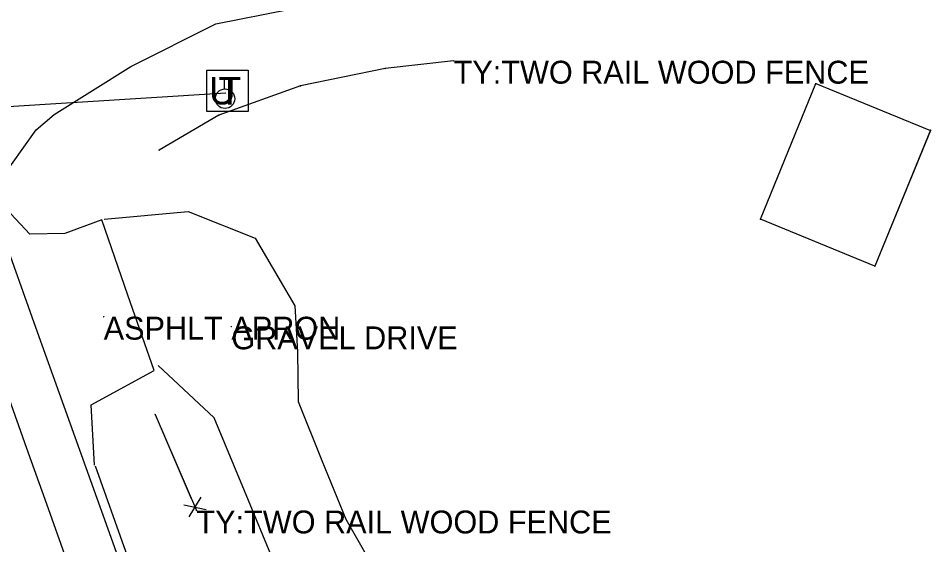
# Model space of a CAD drawing. Extents: x 1050807 to 1053552, y 395828 to 398415.
# Drawn here: x 1052115 to 1052314.1, y 397684.6 to 397799.4 of the extents above; entities that cross this region are included whole.
import ezdxf

# ---------------------------------------------------------------- set-up
doc = ezdxf.new("R2010")
doc.units = 0
for name, color, linetype in [('Default', 7, 'Continuous'), ('S_BUILDING', 7, 'Continuous'), ('S_DRIVEWAY', 7, 'Continuous'), ('S_EDGE_PAVEMENT', 7, 'Continuous'), ('S_FENCE', 7, 'Continuous'), ('S_FENCE_ANNOT', 7, 'Continuous'), ('S_MSC_PT_SYM', 7, 'Continuous'), ('S_PAVEMENT_CROWN', 7, 'Continuous'), ('S_SHOULDER', 7, 'Continuous'), ('S_STR_PT_SYM', 7, 'Continuous'), ('S_SURVEY_TEXT_ANNOT', 7, 'Continuous'), ('S_TELEPHONE_UTILITIES', 7, 'Continuous'), ('S_UNDERGROUND_CABLE', 7, 'Continuous'), ('S_UTILITY_POLE', 7, 'Continuous')]:
    doc.layers.add(name, color=color, linetype=linetype)

msp = doc.modelspace()

# ---------------------------------------------------------------- linework, layer by layer
at = {"layer": 'S_BUILDING'}
for p, q in [((1052276.93, 397755.59), (1052289.06, 397785.2)), ((1052289.06, 397785.2), (1052314.05, 397774.96)), ((1052314.07, 397775.01), (1052301.91, 397745.35)), ((1052314.05, 397774.96), (1052301.91, 397745.35)), ((1052301.91, 397745.35), (1052276.93, 397755.59))]:
    msp.add_line(p, q, dxfattribs=at)
at = {"layer": 'S_DRIVEWAY'}
for points in [[(1052133.67, 397755.55), (1052152.05, 397757.22), (1052166.68, 397751.47), (1052175.35, 397736.7), (1052175.93, 397726.65), (1052176.02, 397715.78), (1052181.24, 397702.97), (1052186.46, 397690.16), (1052194.09, 397676.73), (1052201.72, 397663.29), (1052214.22, 397644.23), (1052221.51, 397635.12)], [(1052214.75, 397627.33), (1052200.49, 397644.3), (1052189.4, 397657.53), (1052178.32, 397670.77), (1052170.98, 397680.3), (1052164.34, 397696.29), (1052157.7, 397712.28), (1052145.51, 397723.65)]]:
    msp.add_lwpolyline(points, dxfattribs=at)
at = {"layer": 'S_EDGE_PAVEMENT'}
for points in [[(1052214.47, 397461.1), (1052206.55, 397483.78), (1052198.62, 397506.45), (1052191.75, 397526.31), (1052184.88, 397546.16), (1052177.39, 397567.38), (1052169.89, 397588.61), (1052165.61, 397600.65), (1052161.33, 397612.68), (1052157.05, 397624.72), (1052152.78, 397636.76), (1052148.47, 397648.84), (1052144.17, 397660.93), (1052139.87, 397673.02), (1052135.57, 397685.11), (1052127.35, 397708.02), (1052119.13, 397730.93), (1052110.86, 397754.03), (1052102.59, 397777.13), (1052095.71, 397795.99), (1052088.82, 397814.85)], [(1052131.61, 397701.92), (1052130.86, 397715.11), (1052144.6, 397722.59), (1052138.9, 397739), (1052133.2, 397755.41), (1052125.14, 397752.48), (1052117.48, 397752.33), (1052113.34, 397756.77), (1052110.71, 397763.72), (1052118.88, 397775.06), (1052122.78, 397778.38), (1052139.51, 397788.91), (1052158.09, 397798.17), (1052174.27, 397801.39)]]:
    msp.add_lwpolyline(points, dxfattribs=at)
at = {"layer": 'S_FENCE'}
for p, q in [((1052195.02, 397788.44), (1052176.57, 397784.66)), ((1052209.98, 397790.14), (1052195.02, 397788.44)), ((1052176.57, 397784.66), (1052158.73, 397778.28)), ((1052158.73, 397778.28), (1052145.72, 397770.67)), ((1052144.85, 397712.99), (1052153.84, 397692.03)), ((1052154.84, 397694.91), (1052152.2, 397690.66)), ((1052154.84, 397694.91), (1052152.2, 397690.66)), ((1052151.07, 397693.29), (1052155.97, 397692.27)), ((1052151.07, 397693.29), (1052155.97, 397692.27))]:
    msp.add_line(p, q, dxfattribs=at)
for points in [[(1052195.02, 397788.44), (1052176.57, 397784.66)], [(1052195.02, 397788.44), (1052176.57, 397784.66)], [(1052209.98, 397790.14), (1052195.02, 397788.44)], [(1052209.98, 397790.14), (1052195.02, 397788.44)], [(1052176.57, 397784.66), (1052158.73, 397778.28)], [(1052176.57, 397784.66), (1052158.73, 397778.28)], [(1052158.73, 397778.28), (1052145.72, 397770.67)], [(1052158.73, 397778.28), (1052145.72, 397770.67)], [(1052144.85, 397712.99), (1052152.73, 397694.62)], [(1052144.85, 397712.99), (1052152.73, 397694.62)]]:
    msp.add_lwpolyline(points, dxfattribs=at)
at = {"layer": 'S_MSC_PT_SYM'}
for points in [[(1052195.02, 397788.44), (1052195.02, 397788.49), (1052195.02, 397788.44), (1052194.97, 397788.44), (1052195.02, 397788.44), (1052195.02, 397788.39), (1052195.02, 397788.44), (1052195.07, 397788.44)], [(1052209.98, 397790.14), (1052209.98, 397790.19), (1052209.98, 397790.14), (1052209.93, 397790.14), (1052209.98, 397790.14), (1052209.98, 397790.09), (1052209.98, 397790.14), (1052210.03, 397790.14)], [(1052176.57, 397784.66), (1052176.57, 397784.71), (1052176.57, 397784.66), (1052176.52, 397784.66), (1052176.57, 397784.66), (1052176.57, 397784.61), (1052176.57, 397784.66), (1052176.62, 397784.66)], [(1052158.73, 397778.28), (1052158.73, 397778.33), (1052158.73, 397778.28), (1052158.68, 397778.28), (1052158.73, 397778.28), (1052158.73, 397778.23), (1052158.73, 397778.28), (1052158.78, 397778.28)], [(1052145.72, 397770.67), (1052145.72, 397770.72), (1052145.72, 397770.67), (1052145.67, 397770.67), (1052145.72, 397770.67), (1052145.72, 397770.62), (1052145.72, 397770.67), (1052145.77, 397770.67)], [(1052133.6, 397734.3), (1052133.6, 397734.35), (1052133.6, 397734.3), (1052133.55, 397734.3), (1052133.6, 397734.3), (1052133.6, 397734.25), (1052133.6, 397734.3), (1052133.65, 397734.3)], [(1052161.46, 397732.2), (1052161.46, 397732.25), (1052161.46, 397732.2), (1052161.41, 397732.2), (1052161.46, 397732.2), (1052161.46, 397732.15), (1052161.46, 397732.2), (1052161.51, 397732.2)], [(1052144.85, 397712.99), (1052144.85, 397713.04), (1052144.85, 397712.99), (1052144.8, 397712.99), (1052144.85, 397712.99), (1052144.85, 397712.94), (1052144.85, 397712.99), (1052144.9, 397712.99)], [(1052153.84, 397692.03), (1052153.84, 397692.08), (1052153.84, 397692.03), (1052153.79, 397692.03), (1052153.84, 397692.03), (1052153.84, 397691.98), (1052153.84, 397692.03), (1052153.89, 397692.03)]]:
    msp.add_lwpolyline(points, dxfattribs=at)
at = {"layer": 'S_PAVEMENT_CROWN'}
msp.add_lwpolyline([(1052205.81, 397457.74), (1052201.49, 397469.54), (1052197.18, 397481.35), (1052192.86, 397493.15), (1052188.55, 397504.96), (1052180.47, 397527.64), (1052172.39, 397550.33), (1052164.11, 397573.46), (1052155.84, 397596.59), (1052149.3, 397615.07), (1052142.77, 397633.56), (1052138.44, 397645.49), (1052134.12, 397657.43), (1052129.8, 397669.37), (1052125.47, 397681.31), (1052121.16, 397693.43), (1052116.84, 397705.56), (1052112.53, 397717.68), (1052108.21, 397729.81), (1052100.29, 397752.14), (1052092.37, 397774.47), (1052083.81, 397797.39), (1052075.25, 397820.32)], dxfattribs=at)
at = {"layer": 'S_SHOULDER'}
msp.add_lwpolyline([(1052215.81, 397461.5), (1052211.2, 397477.1), (1052206.6, 397492.7), (1052202.49, 397504.78), (1052198.38, 397516.87), (1052193.22, 397530.8), (1052188.06, 397544.72), (1052180.04, 397566.9), (1052172.01, 397589.08), (1052167.73, 397601.15), (1052163.45, 397613.21), (1052159.17, 397625.28), (1052154.9, 397637.34), (1052146.66, 397660.22), (1052138.43, 397683.1), (1052131.84, 397701.67)], dxfattribs=at)
at = {"layer": 'S_STR_PT_SYM'}
for points in [[(1052289.06, 397785.2), (1052289.06, 397785.25), (1052289.06, 397785.2), (1052289.01, 397785.2), (1052289.06, 397785.2), (1052289.06, 397785.15), (1052289.06, 397785.2), (1052289.11, 397785.2)], [(1052314.05, 397774.96), (1052314.05, 397775.01), (1052314.05, 397774.96), (1052314, 397774.96), (1052314.05, 397774.96), (1052314.05, 397774.91), (1052314.05, 397774.96), (1052314.1, 397774.96)], [(1052314.07, 397775.01), (1052314.07, 397775.06), (1052314.07, 397775.01), (1052314.02, 397775.01), (1052314.07, 397775.01), (1052314.07, 397774.96), (1052314.07, 397775.01), (1052314.12, 397775.01)], [(1052276.93, 397755.59), (1052276.93, 397755.64), (1052276.93, 397755.59), (1052276.88, 397755.59), (1052276.93, 397755.59), (1052276.93, 397755.54), (1052276.93, 397755.59), (1052276.98, 397755.59)], [(1052301.91, 397745.35), (1052301.91, 397745.4), (1052301.91, 397745.35), (1052301.86, 397745.35), (1052301.91, 397745.35), (1052301.91, 397745.3), (1052301.91, 397745.35), (1052301.96, 397745.35)], [(1052301.91, 397745.35), (1052301.91, 397745.4), (1052301.91, 397745.35), (1052301.86, 397745.35), (1052301.91, 397745.35), (1052301.91, 397745.3), (1052301.91, 397745.35), (1052301.96, 397745.35)]]:
    msp.add_lwpolyline(points, dxfattribs=at)
at = {"layer": 'S_TELEPHONE_UTILITIES'}
msp.add_lwpolyline([(1052156.12, 397779.08), (1052156.12, 397788.08), (1052165.12, 397788.08), (1052165.12, 397779.08)], close=True, dxfattribs=at)
at = {"layer": 'S_UNDERGROUND_CABLE'}
msp.add_line((1052108.22, 397779.87), (1052160.23, 397783.16), dxfattribs=at)
at = {"layer": 'S_UTILITY_POLE'}
msp.add_line((1052159.96, 397783.99), (1052159.96, 397786.1), dxfattribs=at)
msp.add_circle((1052160.08, 397781.85), 2.13, dxfattribs=at)

# ---------------------------------------------------------------- texts
at = {"layer": 'Default'}
msp.add_text('U', height=6, dxfattribs=at).set_placement((1052156.6, 397780.61))
at = {"layer": 'S_FENCE_ANNOT'}
for p in [(1052209.98, 397785.14), (1052153.84, 397687.03)]:
    msp.add_text('TY:TWO RAIL WOOD FENCE', height=5, dxfattribs=at).set_placement(p)
at = {"layer": 'S_SURVEY_TEXT_ANNOT'}
for s, p in [('ASPHLT APRON', (1052133.6, 397729.3)), ('GRAVEL DRIVE', (1052161.46, 397727.2))]:
    msp.add_text(s, height=5, dxfattribs=at).set_placement(p)
at = {"layer": 'S_TELEPHONE_UTILITIES'}
msp.add_text('T', height=6, dxfattribs=at).set_placement((1052158.68, 397780.58))

doc.saveas('drawing.dxf')
